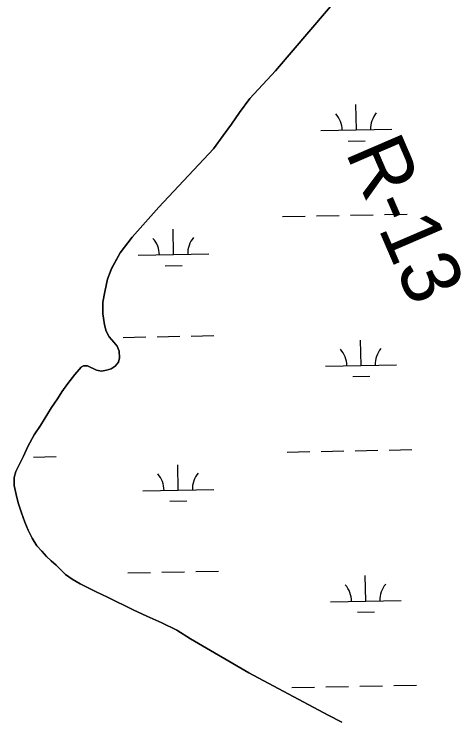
# Model space of a CAD drawing. Extents: x 3989314 to 4027622, y 243956 to 270014.
# Drawn here: x 4010321 to 4010953, y 259015 to 260013 of the extents above; entities that cross this region are included whole.
import ezdxf

# ---------------------------------------------------------------- set-up
doc = ezdxf.new("R2010")
doc.units = 0
for name, color, linetype in [('V-RIVR-EDGE', 7, 'Continuous'), ('V-RIVR-RANG-IDEN', 7, 'Continuous'), ('V-WETL-SWMP', 7, 'Continuous')]:
    doc.layers.add(name, color=color, linetype=linetype)

msp = doc.modelspace()

# ---------------------------------------------------------------- linework, layer by layer
at = {"layer": 'V-RIVR-EDGE'}
for points in [[(4010809.09, 260072.38), (4010715.11, 259961.93), (4010689.83, 259932.92), (4010653.92, 259893.43), (4010639.04, 259873.71), (4010628.05, 259857.47), (4010616.27, 259841.45), (4010602.62, 259822.49), (4010525.51, 259740.07), (4010487.74, 259698.05), (4010470.81, 259675.99), (4010458.46, 259653.4), (4010453.08, 259638.61), (4010449.22, 259620.78), (4010446.43, 259605.91), (4010446.21, 259589.78), (4010447.23, 259583.38), (4010448.98, 259574.17), (4010451.12, 259564.95), (4010455.49, 259557.06), (4010462.07, 259549.71), (4010466.7, 259543.82), (4010469.69, 259536.76), (4010470.04, 259527.39), (4010468.48, 259521.26), (4010463.96, 259515.8), (4010458.28, 259512.16), (4010451.65, 259509.95), (4010444.44, 259508.75), (4010437.7, 259509.93), (4010424.91, 259516.04), (4010419.14, 259516.2), (4010415.7, 259514.1), (4010406.86, 259503.97), (4010396.96, 259491.09), (4010388.68, 259479.55), (4010382.44, 259469.56), (4010374.14, 259457.23), (4010358.72, 259431.74), (4010349.6, 259418.64), (4010340.4, 259402.15), (4010334.66, 259388.76), (4010327.31, 259374.61), (4010323.52, 259366.94), (4010321.3, 259358.43), (4010321.4, 259347.07), (4010324.25, 259334.45), (4010327.13, 259322.82), (4010331.53, 259308.55), (4010336.36, 259295.68), (4010341.03, 259283.99), (4010346.72, 259273.09), (4010353.2, 259262.16), (4010360.17, 259254.4), (4010367.14, 259247.04), (4010373.75, 259240.69), (4010380.77, 259234.93), (4010393.56, 259221.83)], [(4010393.56, 259221.83), (4010403.34, 259214.8), (4010414.32, 259208.33), (4010423.96, 259203.89), (4010436.93, 259196.97), (4010453.07, 259189.57), (4010489.06, 259171.88), (4010508.53, 259162.79), (4010529.6, 259153.26), (4010550.84, 259142.93), (4010570.03, 259130.67), (4010652.23, 259082.86), (4010764.19, 259023.1), (4010783.85, 259013.21)]]:
    msp.add_lwpolyline(points, dxfattribs=at)
at = {"layer": 'V-WETL-SWMP'}
for p, q in [((4010804.16, 259849.25), (4010803.45, 259885.24)), ((4010754.17, 259848.25), (4010854.15, 259850.24)), ((4010792.47, 259833.58), (4010816.47, 259834.06)), ((4010699.73, 259727.07), (4010731.73, 259727.71)), ((4010747.72, 259728.03), (4010779.72, 259728.66)), ((4010795.71, 259728.98), (4010827.71, 259729.62)), ((4010843.7, 259729.94), (4010875.7, 259730.58)), ((4010546.18, 259673.26), (4010545.46, 259709.25)), ((4010496.19, 259672.26), (4010596.17, 259674.25)), ((4010534.49, 259657.59), (4010558.49, 259658.07)), ((4010475.09, 259556.39), (4010507.08, 259557.02)), ((4010523.08, 259557.34), (4010555.07, 259557.98)), ((4010571.07, 259558.3), (4010603.06, 259558.94)), ((4010810.79, 259516.64), (4010810.07, 259552.63)), ((4010760.8, 259515.64), (4010860.78, 259517.63)), ((4010799.1, 259500.97), (4010823.1, 259501.45)), ((4010706.36, 259394.46), (4010738.35, 259395.1)), ((4010754.35, 259395.42), (4010786.34, 259396.06)), ((4010802.34, 259396.37), (4010834.34, 259397.01)), ((4010850.33, 259397.33), (4010882.33, 259397.97)), ((4010348.52, 259387.33), (4010380.52, 259387.97)), ((4010552.81, 259340.65), (4010552.09, 259376.64)), ((4010502.82, 259339.65), (4010602.8, 259341.65)), ((4010541.12, 259324.98), (4010565.12, 259325.46)), ((4010577.7, 259225.69), (4010609.69, 259226.33)), ((4010481.72, 259223.78), (4010513.71, 259224.42)), ((4010529.71, 259224.73), (4010561.7, 259225.37)), ((4010817.42, 259184.03), (4010816.7, 259220.02)), ((4010767.43, 259183.03), (4010867.41, 259185.02)), ((4010805.73, 259168.36), (4010829.72, 259168.84)), ((4010712.99, 259061.85), (4010744.98, 259062.49)), ((4010760.98, 259062.81), (4010792.97, 259063.45)), ((4010808.97, 259063.77), (4010840.96, 259064.4)), ((4010856.96, 259064.72), (4010888.95, 259065.36))]:
    msp.add_line(p, q, dxfattribs=at)
for points in [[(4010349.6, 259418.64), (4010358.72, 259431.74), (4010374.14, 259457.23), (4010382.44, 259469.56), (4010388.68, 259479.55), (4010396.96, 259491.09), (4010406.86, 259503.97), (4010415.7, 259514.1), (4010419.14, 259516.2), (4010424.91, 259516.04), (4010437.7, 259509.92), (4010444.44, 259508.75), (4010451.65, 259509.95), (4010458.28, 259512.16), (4010463.96, 259515.8), (4010468.48, 259521.26), (4010470.04, 259527.39), (4010469.69, 259536.76), (4010466.69, 259543.82), (4010462.07, 259549.72), (4010455.49, 259557.06), (4010451.12, 259564.95), (4010448.98, 259574.17), (4010447.23, 259583.38), (4010446.2, 259589.78), (4010446.44, 259605.91), (4010449.22, 259620.78), (4010453.08, 259638.61), (4010458.46, 259653.41), (4010470.81, 259675.99), (4010487.74, 259698.05), (4010525.51, 259740.07), (4010602.62, 259822.49), (4010616.27, 259841.45), (4010628.05, 259857.47), (4010639.04, 259873.71), (4010653.91, 259893.43), (4010689.83, 259932.92), (4010715.11, 259961.93), (4010809.09, 260072.38)], [(4010783.85, 259013.21), (4010764.19, 259023.1), (4010652.23, 259082.86), (4010570.03, 259130.67), (4010550.84, 259142.93), (4010529.6, 259153.26), (4010508.53, 259162.79), (4010489.05, 259171.88), (4010453.07, 259189.57), (4010436.93, 259196.97), (4010423.97, 259203.89), (4010414.32, 259208.33), (4010403.34, 259214.8), (4010393.56, 259221.83), (4010380.77, 259234.93), (4010373.75, 259240.69), (4010367.14, 259247.04), (4010360.17, 259254.4), (4010353.2, 259262.16), (4010346.72, 259273.09), (4010341.03, 259284), (4010336.37, 259295.68), (4010331.53, 259308.55), (4010327.13, 259322.82), (4010324.25, 259334.45), (4010321.4, 259347.07), (4010321.3, 259358.43), (4010323.52, 259366.94), (4010327.31, 259374.61), (4010334.66, 259388.76), (4010340.4, 259402.15), (4010349.6, 259418.64)]]:
    msp.add_lwpolyline(points, dxfattribs=at)
for centre, start, end in [((4010748.92, 259848.62), 0.36988, 41.91354), ((4010859.38, 259850.82), 140.36987, 181.91353), ((4010490.94, 259672.63), 0.36988, 41.91354), ((4010601.4, 259674.83), 140.36987, 181.91353), ((4010755.55, 259516.01), 0.36988, 41.91354), ((4010866.01, 259518.21), 140.36987, 181.91353), ((4010497.57, 259340.02), 0.36988, 41.91354), ((4010608.03, 259342.22), 140.36987, 181.91353), ((4010762.18, 259183.4), 0.36988, 41.91354), ((4010872.64, 259185.6), 140.36987, 181.91353)]:
    msp.add_arc(centre, 35.25, start, end, dxfattribs=at)

# ---------------------------------------------------------------- texts
at = {"layer": 'V-RIVR-RANG-IDEN'}
msp.add_text('R-13 ', height=83, rotation=293.3335, dxfattribs=at).set_placement((4010788.14, 259818.11))

doc.saveas('drawing.dxf')
